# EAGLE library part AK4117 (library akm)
Digital Audio Receiver (DIR) Low Power, 24-Bit, 192 kHz
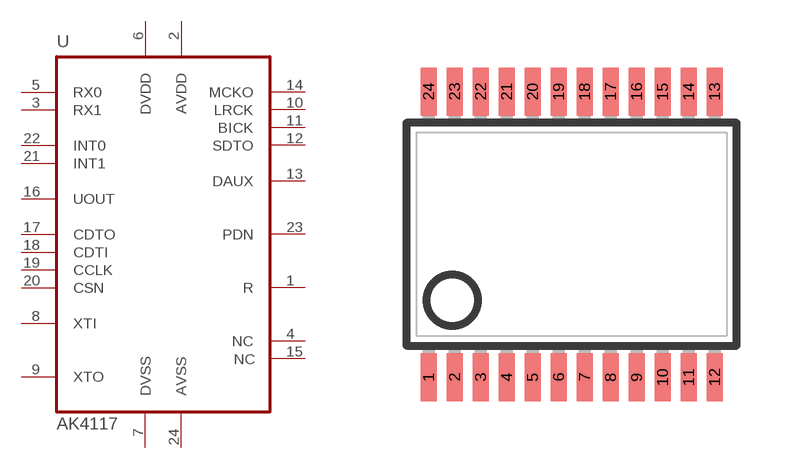
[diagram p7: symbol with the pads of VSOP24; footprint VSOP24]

Designator prefix U

## AK4117  [VSOP24]
1  R  pas
2  AVDD  pwr
3  RX1  in
4  NC  in
5  RX0  in
6  DVDD  pwr
7  DVSS  pwr
8  XTI  in
9  XTO  out
10  LRCK
11  BICK
12  SDTO  out
13  DAUX  out
14  MCKO  in
15  NC1  in
16  UOUT  out
17  CDTO  out
18  CDTI  in
19  CCLK  in
20  CSN  in
21  INT1  out
22  INT0  out
23  PDN  in
24  AVSS  pwr

## Footprint VSOP24 (pad centres in mm)
VSOP24 7.8 x 5.6 mm, pitch .65 mm
smd 0.4 x 1.2: 1 -3.575,-3.57; 2 -2.925,-3.57; 3 -2.275,-3.57; 4 -1.625,-3.57; 5 -0.975,-3.57; 6 -0.325,-3.57; 7 0.325,-3.57; 8 0.975,-3.57; 9 1.625,-3.57; 10 2.275,-3.57; 11 2.925,-3.57; 12 3.575,-3.57; 13 3.575,3.57; 14 2.925,3.57; 15 2.275,3.57; 16 1.625,3.57; 17 0.975,3.57; 18 0.325,3.57; 19 -0.325,3.57; 20 -0.975,3.57; 21 -1.625,3.57; 22 -2.275,3.57; 23 -2.925,3.57; 24 -3.575,3.57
